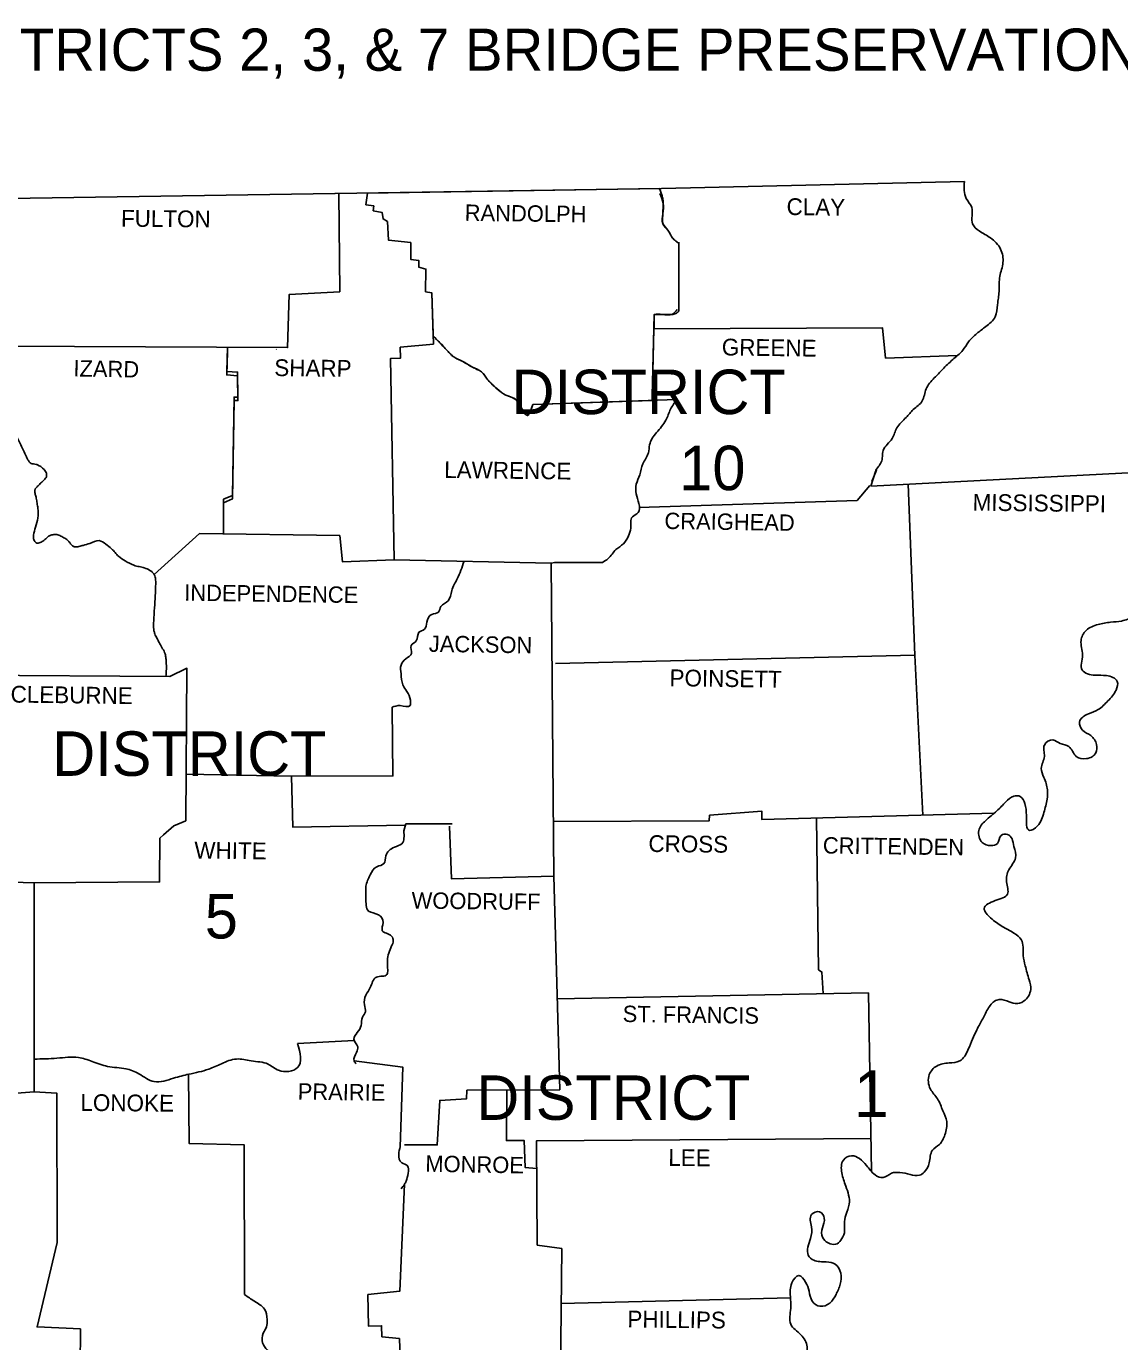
# Model space of a CAD drawing. Extents: x -12863 to 18921, y -8840 to 11152.
# Drawn here: x 13760 to 16502, y 7447 to 10747 of the extents above; entities that cross this region are included whole.
import ezdxf

# ---------------------------------------------------------------- set-up
doc = ezdxf.new("R2010")
doc.units = 0
for name, color, linetype in [('Level 1', 7, 'Continuous'), ('Level 2', 7, 'Continuous'), ('Level 3', 7, 'Continuous'), ('Level 42', 7, 'Continuous')]:
    doc.layers.add(name, color=color, linetype=linetype)

msp = doc.modelspace()

# ---------------------------------------------------------------- linework, layer by layer
at = {"layer": 'Level 1'}
for p, q in [((14615.8, 10328.9), (15347.9, 10340.3)), ((15396.7, 10202.4), (15396.7, 10032.6)), ((15878.1, 9593.9), (15889.9, 9630.1)), ((15881, 9605.6), (15892.8, 9634)), ((14711.9, 8746.6), (14828.3, 8746.6))]:
    msp.add_line(p, q, dxfattribs=at)
for points in [[(10745.4, 10313), (12327.5, 10312), (13715.8, 10314.9), (15353.7, 10340.4), (16112.9, 10358)], [(14544.5, 10327.8), (14546.5, 10081.1), (14419.3, 10074.3), (14415.4, 9941.2), (13702.7, 9945.1)], [(14780.7, 9970.4), (14777.4, 10078.2), (14761.8, 10081.1), (14762.7, 10137.9), (14745.1, 10142.7), (14745.1, 10159.4), (14724.6, 10162.3), (14724.6, 10204.4), (14668.8, 10210.3), (14665.9, 10257.2), (14655.1, 10264.1), (14653.1, 10279.7), (14630.6, 10284.6), (14631.6, 10296.4), (14612.1, 10299.3), (14615.8, 10328.9)], [(13715.8, 10309.1), (13717.8, 10076.2), (13701.2, 10075.2), (13704.1, 9831.6), (13635.6, 9821.8), (13641.5, 9756.3), (13665, 9725.9), (13663, 9648.7), (13529.9, 9643.8), (13525, 9524.4), (13403.7, 9520.5), (13397.9, 9375.7), (13404.7, 9363.9), (13407.6, 9133), (13617, 9119.3), (13614.1, 8603.7), (13780.4, 8598.8), (13780.4, 8074.4), (13649.3, 8064.6), (13639.5, 7949.2), (13419.4, 7948.2)], [(14615, 10322.8), (14612.1, 10299.3), (14631.6, 10296.4), (14630.6, 10284.6), (14653.1, 10279.7), (14655.1, 10264.1), (14665.9, 10257.2), (14668.8, 10210.3), (14724.6, 10204.4), (14724.6, 10162.3), (14745.1, 10159.4), (14745.1, 10142.7), (14762.7, 10137.9), (14761.8, 10081.1), (14777.4, 10078.2), (14781.3, 9950), (14698.2, 9942.2), (14699.1, 9914.8), (14673.7, 9913.8), (14682.5, 9408.9), (15076.8, 9400.1), (15083.6, 8615.5), (14826.3, 8608.6), (14821.4, 8740.7)], [(15396.7, 10205.4), (15396.7, 10040)], [(15335.1, 10024.4), (15329.9, 9808.8), (15030.8, 9798.3)], [(15330.2, 9819.9), (15335.1, 10024.4), (15335.1, 9988.2), (15907.5, 9991.1), (15915.3, 9914.8), (16094.8, 9921.3)], [(14264.8, 9942), (14262.8, 9881.5), (14290.2, 9879.6), (14291.1, 9816.9), (14281.4, 9816.9), (14277.4, 9570.4), (14254.9, 9560.6), (14254.9, 9478.4)], [(14387, 9936.3), (14388, 9937.3)], [(14264.7, 9929.5), (14262.8, 9872.7), (14290.2, 9870.7), (14291.1, 9808.1), (14281.4, 9808.1), (14277.4, 9561.6), (14254.9, 9551.8), (14254.9, 9473.7)], [(15030.8, 9798.3), (15391.5, 9811)], [(15878.1, 9593.9), (16620.7, 9632)], [(15296.1, 9539.9), (15843.9, 9557.7), (15876.2, 9594.8)], [(15971.8, 9598.7), (15988.7, 9169.2), (16008.6, 8768.4)], [(14080.7, 9371.9), (14194.3, 9474.5), (14546.5, 9469.6), (14553.3, 9404), (14682.5, 9409)], [(15205, 9402.1), (15085.6, 9402.1), (15076.8, 9400.1)], [(15988.7, 9169.2), (15087.6, 9148.7)], [(13617, 9119.3), (14119.9, 9116.4), (14163, 9136.9), (14160, 8754.4), (14130.7, 8741.7), (14104.3, 8719.2), (14095.5, 8710.4), (14094.5, 8600.8), (13780.4, 8598.8)], [(14677.6, 9039.1), (14679.6, 8866.9), (14425.2, 8865.9), (14160.9, 8870.9)], [(14425.2, 8865.9), (14429.1, 8737.8), (14710.8, 8742.8)], [(15082.5, 8752.4), (15473.1, 8754.4), (15474, 8768.1), (15605.1, 8777.9), (15605.1, 8757.3), (16188, 8773.3)], [(14711.9, 8746.6), (14707, 8728.9)], [(15742.1, 8761.1), (15747, 8380.6), (15755.8, 8374.8), (15758.9, 8320.6)], [(15083.6, 8615.5), (15098.3, 8079.3), (14865.5, 8078.3), (14864.5, 8056.8), (14797, 8052.9), (14791.1, 7941.3), (14708.9, 7941.3)], [(15092.1, 8307.2), (15872.2, 8322.9)], [(15872.2, 8322.9), (15880.4, 7874.7)], [(14440.8, 8195.7), (14582.7, 8202.6)], [(14582.7, 8151.7), (14705, 8136), (14698.2, 7936.4)], [(14166.9, 8119.4), (14168.8, 7944.3), (14306.8, 7941.3), (14307.8, 7565.6)], [(13780.4, 8074.4), (13837.2, 8070.5), (13838.1, 7696.7), (13787.3, 7484.4), (13895.9, 7479.5), (13894.8, 7292.5)], [(14965.3, 8078.7), (14964.3, 7952.1), (15009.3, 7952.1), (15011.2, 7884.6), (15040.1, 7881.6)], [(15095.4, 7084.2), (15171.7, 7089.1), (15170.7, 7287.8), (15099.3, 7292.6), (15103.2, 7681.1), (15041.6, 7689.9), (15039.6, 7951.1), (15878.9, 7957)], [(14708.9, 7842.5), (14697.2, 7574.4), (14616.9, 7565.6), (14618.9, 7486.4), (14651.2, 7487.3), (14652.2, 7460), (14696.2, 7455.1), (14697.6, 7407.8)], [(15101.8, 7543), (15676.7, 7557.3)]]:
    msp.add_lwpolyline(points, dxfattribs=at)
for points in [[(15347.9, 10340.3), (15349.9, 10335.8), (15351.7, 10331.2), (15354.8, 10322), (15356.8, 10312.6), (15357.2, 10310.3), (15357.4, 10307.9), (15357.6, 10303.2), (15357.5, 10296.6), (15357.2, 10290), (15356.9, 10283.4), (15356.6, 10276.8), (15356.5, 10273.7), (15356, 10264.6), (15355.9, 10258.4), (15356.2, 10255.4), (15356.4, 10253.9), (15356.5, 10253.1), (15356.6, 10252.3), (15357.4, 10249.9), (15357.9, 10248.7), (15358.6, 10247.6), (15360.3, 10245.5), (15362, 10243.6), (15365.9, 10239.7), (15367.8, 10237.8), (15369.3, 10235.7), (15372.5, 10230.6), (15375.5, 10225.4), (15378.6, 10220.2), (15380.3, 10217.6), (15382.1, 10215.1), (15384.2, 10212.7), (15386.6, 10210.4), (15389.1, 10208.4), (15396.7, 10202.4)], [(16112.9, 10358), (16117.8, 10314.9), (16131.5, 10292.4), (16133.5, 10251.3), (16150.1, 10233.7), (16178.5, 10216.1), (16203.9, 10187.8), (16209.8, 10154.5), (16202, 10120.2), (16200, 10082.1), (16196.1, 10048.8), (16190.2, 10018.5), (16166.7, 9994), (16144.2, 9976.4), (16123.7, 9955.9), (16109, 9934.3), (16083.6, 9910.9), (16058.1, 9886.4), (16037.6, 9864.9), (16017, 9837.5), (16007.3, 9807.2), (15984.8, 9785.6), (15967.1, 9766.1), (15943.7, 9739.6), (15931.9, 9713.2), (15909.4, 9682.9), (15904.5, 9653.5), (15889.9, 9630.1), (15888.9, 9626.1)], [(15348.8, 10327.7), (15357.6, 10303.2), (15356.6, 10276.8), (15356.6, 10252.3), (15369.3, 10235.7), (15382.1, 10215.1), (15391.8, 10206.3)], [(15392.8, 10037.1), (15380.1, 10024.4), (15355.6, 10024.4), (15335.1, 10024.4)], [(15396.7, 10032.6), (15394.9, 10030.9), (15393, 10029.3), (15389, 10026.7), (15384.6, 10025), (15382.4, 10024.5), (15381.3, 10024.4), (15380.1, 10024.4), (15355.6, 10024.4), (15335.1, 10024.4)], [(15030.8, 9798.3), (15029.3, 9794.1), (15027.6, 9789.2), (15023.8, 9779.4), (15019.6, 9772.4), (15017.4, 9771.1), (15016.3, 9771.2), (15015.2, 9771.9), (15014.7, 9772.4), (15014.3, 9772.8), (15013.3, 9773.8), (15011.5, 9776), (15007.8, 9781.2), (15004.1, 9786.9), (15002.3, 9789.8), (15000.5, 9792.5), (14997.8, 9796.7), (14995.2, 9800.9), (14992.6, 9805.1), (14989.7, 9809.1), (14986.6, 9812.2), (14982.8, 9814.5), (14974.3, 9817.8), (14965.4, 9820.6), (14957.4, 9824.8), (14952.2, 9828.7), (14947, 9832.8), (14941.8, 9837), (14936.9, 9841.4), (14926.4, 9851.5), (14916.3, 9861.9), (14914.4, 9864.2), (14912.7, 9866.6), (14909.4, 9871.7), (14906, 9876.5), (14901.7, 9880.5), (14900.3, 9881.4), (14899, 9882.2), (14890.5, 9886.6), (14884.8, 9889.3), (14879.2, 9892.3), (14866.4, 9899.6), (14853.7, 9906.9), (14848.3, 9909.6), (14842.7, 9911.9), (14837.2, 9914.4), (14832.2, 9917.7), (14830.9, 9918.8), (14829.7, 9919.9), (14827.3, 9922.1), (14822.7, 9926.8), (14813.6, 9936.3), (14797.1, 9953.2), (14780.7, 9970.4)], [(14792.1, 9958.8), (14813.6, 9936.3), (14832.2, 9917.7), (14853.7, 9906.9), (14879.2, 9892.3), (14901.7, 9880.5), (14916.3, 9861.9), (14936.9, 9841.4), (14957.4, 9824.8), (14989.7, 9809.1), (15000.5, 9792.5), (15015.2, 9771.9), (15030.8, 9798.3)], [(15391.5, 9811), (15376.2, 9786.6), (15364.4, 9759.2), (15341, 9727.9), (15323.4, 9697.6), (15320.4, 9677), (15306.7, 9649.6), (15298.9, 9622.2), (15290.1, 9598.8), (15290.1, 9574.3), (15296.9, 9549.8), (15295, 9527.3), (15280.3, 9516.6), (15276.4, 9488.2), (15270.5, 9468.6), (15257.8, 9449.1), (15239.2, 9434.4), (15219.6, 9411.9), (15205, 9402.1)], [(13665, 9725.9), (13674.5, 9722.3), (13684.4, 9720.3), (13694.3, 9719.5), (13704.1, 9719.1), (13710.2, 9721.1), (13716.3, 9725.5), (13722.1, 9728.9), (13724.9, 9729.2), (13727.6, 9727.9), (13733.1, 9722.3), (13737.4, 9716), (13741, 9709.3), (13744.2, 9702.5), (13753, 9682.9), (13759.8, 9668.5), (13763.5, 9661.4), (13765.5, 9657.9), (13767.7, 9654.5), (13772.3, 9650.8), (13778.5, 9649.2), (13785.1, 9648), (13788.3, 9647.1), (13791.2, 9645.7), (13808.8, 9630.1), (13811.3, 9621.6), (13810.7, 9617.2), (13808.8, 9613.4), (13805.1, 9609.4), (13801.1, 9605.6), (13797, 9601.8), (13793.1, 9597.8), (13791.4, 9595.9), (13785.8, 9590.4), (13782.8, 9586.5), (13781.8, 9584.4), (13781.4, 9582.1), (13781.7, 9577.5), (13782.8, 9572.9), (13784.2, 9568.2), (13785.3, 9563.5), (13787.4, 9550.8), (13789.2, 9538.1), (13789.2, 9513.6), (13783.3, 9491.1), (13778.5, 9470.6), (13778, 9466.1), (13778.6, 9461.7), (13780.4, 9457.3), (13781.7, 9455.1), (13783.3, 9453), (13785.4, 9451.3), (13787.6, 9450.5), (13792.5, 9451.2), (13801.9, 9455.9), (13806.8, 9459.4), (13811.5, 9463.6), (13816.2, 9467.7), (13821.5, 9470.6), (13826.5, 9471.8), (13831.8, 9472.3), (13842, 9470.6), (13852.1, 9465.7), (13861.6, 9459.8), (13866.8, 9454.9), (13871.5, 9449), (13876.3, 9443.8), (13879.1, 9442.1), (13880.6, 9441.5), (13882.2, 9441.2), (13892.4, 9442.2), (13902.7, 9445.1), (13919.3, 9450), (13942.8, 9456.9), (13959.5, 9448.1), (13974.1, 9436.3), (13978.6, 9431.8), (13982.9, 9427), (13987.1, 9422.2), (13991.7, 9417.7), (14008.4, 9406), (14029.9, 9395.2), (14036.3, 9393.1), (14043, 9391.7), (14049.7, 9390.3), (14056.3, 9388.4), (14070.2, 9382.4), (14076.1, 9377.9), (14078.6, 9375.1), (14079.8, 9373.5), (14080.8, 9371.8), (14082.4, 9368.2), (14084.7, 9357.6), (14084.9, 9350.5), (14084.7, 9343.4), (14083.7, 9318.9), (14081.8, 9288.6), (14079.8, 9255.3), (14079.4, 9247.2), (14079.4, 9239.1), (14080.4, 9231), (14081.4, 9227), (14082.7, 9223), (14087.9, 9212), (14093.5, 9201.5), (14100.4, 9189), (14107.2, 9176.1), (14110.3, 9164.5), (14110.8, 9158.6), (14111.1, 9152.6), (14111.6, 9134.5), (14110.3, 9116.5)], [(16610, 9631), (16620.7, 9632), (16654, 9596.8), (16668.7, 9567.4), (16690.2, 9550.8), (16714.7, 9542), (16733.2, 9519.5), (16746, 9495), (16739.1, 9473.5), (16711.7, 9471.6), (16681.4, 9466.7), (16652, 9467.6), (16628.6, 9448.1), (16650.1, 9421.7), (16678.4, 9397.2), (16686.3, 9370.8), (16670.6, 9345.3), (16639.3, 9331.6), (16609, 9319.9), (16581.6, 9296.4), (16568.9, 9273.9), (16538.5, 9264.1), (16507.2, 9255.3), (16479.8, 9252.4), (16448.5, 9246.5), (16418.2, 9231.8), (16405.5, 9206.4), (16409.4, 9170.2), (16408.4, 9132.1), (16440.7, 9119.3), (16469.1, 9118.4), (16496.5, 9103.7), (16493.5, 9082.2), (16473, 9054.8), (16448.5, 9033.2), (16424.1, 9022.5), (16401.6, 9001.9), (16409.4, 8981.4), (16429.9, 8967.7), (16444.6, 8945.2), (16442.7, 8924.6), (16419.2, 8910), (16393.7, 8915.8), (16375.1, 8940.3), (16353.6, 8948.1), (16335, 8956.9), (16313.5, 8944.2), (16313.5, 8915.8), (16305.7, 8885.5), (16312.5, 8863), (16321.3, 8831.7), (16320.4, 8808.2), (16312.5, 8774.9), (16295.9, 8740.7), (16276.3, 8729.9), (16268.5, 8767.1), (16264.6, 8797.4), (16252.8, 8815), (16237.2, 8816), (16216.6, 8801.3), (16194.1, 8778.8), (16165.8, 8754.4), (16149.1, 8729.9), (16157.9, 8699.6), (16179.5, 8691.8), (16196.1, 8697.6), (16204.9, 8717.2), (16221.5, 8720.1), (16237.2, 8689.8)], [(14858.1, 9405.1), (14841, 9361), (14827.3, 9331.6), (14818.5, 9306.2), (14799.9, 9291.5), (14794, 9277.8), (14777.4, 9272), (14764.7, 9252.4), (14758.8, 9234.8), (14745.1, 9227), (14738.3, 9205.4), (14725.5, 9193.7), (14726.5, 9174.1), (14711.9, 9160.4), (14700.1, 9144.8), (14700.1, 9123.2), (14705, 9094.9), (14714.8, 9078.2), (14723.6, 9056.7), (14722.6, 9043), (14698.2, 9043), (14677.6, 9039.1)], [(14707, 8728.9), (14702.1, 8696.7), (14683.5, 8687.9), (14662, 8666.3), (14657.1, 8646.8), (14639.4, 8638.9), (14622.8, 8618.4), (14612.1, 8590), (14612.1, 8560.7), (14618.9, 8527.4), (14643.4, 8518.6), (14655.1, 8499), (14653.1, 8478.5), (14676.6, 8464.8), (14680.5, 8453), (14676.6, 8440.3), (14665.9, 8404.1), (14666.8, 8379.7), (14664.9, 8368.9), (14638.5, 8362), (14622.8, 8335.6), (14612.1, 8317), (14608.1, 8292.6), (14611.1, 8275), (14603.2, 8261.3), (14600.3, 8240.7), (14590.5, 8223.1), (14581.7, 8206.5), (14591.5, 8186.9), (14588.6, 8173.2), (14582.7, 8151.7), (14587.6, 8144.8)], [(16237.2, 8689.8), (16241.1, 8661.4), (16224.5, 8631.1), (16218.6, 8600.8), (16221.5, 8570.4), (16190.2, 8553.8), (16162.8, 8534.2), (16178.5, 8510.8), (16207.8, 8489.2), (16237.2, 8472.6), (16255.8, 8456), (16260.7, 8415.9), (16265.6, 8390.4), (16275.3, 8355.2), (16279.3, 8330.7), (16261.6, 8301.4), (16241.1, 8295.5), (16219.6, 8302.4), (16194.1, 8304.3), (16173.6, 8284.8), (16158.9, 8257.4), (16144.2, 8230), (16133.5, 8206.5), (16122.7, 8181), (16101.2, 8151.7), (16074.8, 8146.8), (16043.5, 8139), (16024.9, 8117.4), (16027.8, 8081.2), (16045.4, 8056.8), (16059.1, 8026.5), (16068.9, 8000), (16064, 7966.8), (16050.3, 7942.3), (16032.7, 7927.6), (16024.9, 7896.3), (16012.2, 7872.8), (16000.4, 7865), (15976.9, 7867), (15951.5, 7871.9), (15930, 7869.9), (15909.4, 7859.1), (15888.9, 7866), (15867.4, 7889.5), (15849.7, 7907.1), (15830.2, 7913.9), (15809.6, 7903.2), (15805.7, 7870.9), (15815.5, 7837.6), (15824.3, 7792.6), (15815.5, 7765.2), (15812.6, 7720.2)], [(13780, 8156.5), (13837.2, 8158.5), (13891, 8160.5), (13925.2, 8150.7), (13964.3, 8138), (14010.3, 8132.1), (14042.6, 8119.4), (14080.8, 8099.8), (14129.7, 8108.6), (14167.9, 8118.4), (14217.8, 8131.1), (14250, 8144.8), (14287.2, 8156.6), (14324.4, 8151.7), (14366.5, 8143.9), (14392.9, 8128.2), (14440.8, 8135.1), (14440.8, 8195.7)], [(14698.2, 7936.4), (14694.2, 7916.9), (14702.1, 7896.3), (14715.8, 7889.5), (14717.7, 7869.9), (14712.8, 7850.3), (14708.9, 7842.5), (14700.1, 7830.8)], [(15812.6, 7720.2), (15790.1, 7691.8), (15756.8, 7709.4), (15756.8, 7732.9), (15761.7, 7757.4), (15749.9, 7773), (15729.4, 7766.2), (15729.4, 7735.9), (15727.4, 7706.5), (15721.6, 7664.4), (15735.3, 7651.7), (15766.6, 7647.8), (15789.1, 7641.9), (15802.8, 7619.4), (15801.8, 7592), (15791, 7565.6), (15775.4, 7544.1), (15750.9, 7536.3), (15731.4, 7549), (15723.5, 7574.4), (15714.7, 7596.9), (15698.1, 7613.6), (15680.5, 7595), (15676.6, 7560.7), (15677.5, 7531.4), (15677.5, 7491.3), (15703, 7464.8), (15718.6, 7434.5), (15713.7, 7407.1), (15695.2, 7374.8), (15687.3, 7346.5), (15679.5, 7308.3), (15680.5, 7266.2), (15673.6, 7225.1), (15659.9, 7197.7), (15634.5, 7175.2), (15617.9, 7160.6), (15604.2, 7145.9), (15597.3, 7116.5), (15592.4, 7096), (15573.8, 7071.5), (15559.2, 7069.6), (15547.4, 7079.4), (15543.5, 7096), (15543.5, 7112.6), (15535.7, 7129.3), (15511.2, 7136.1), (15491.6, 7135.1), (15482.8, 7121.4), (15495.6, 7083.3), (15500.4, 7058.8), (15493.6, 7025.5), (15497.5, 7021.6), (15462.3, 7003), (15433.9, 7000.1), (15410.4, 6993.3), (15387.9, 6978.6), (15377.2, 6957.1), (15361.5, 6939.4), (15347.8, 6922.8), (15329.2, 6915), (15308.7, 6918.9), (15281.3, 6921.8), (15265.6, 6902.3), (15270.5, 6873.9), (15289.1, 6857.3), (15316.5, 6849.4), (15344.9, 6851.4), (15372.3, 6854.3), (15397.7, 6840.6), (15392.8, 6814.2), (15368.4, 6801.5), (15332.2, 6797.6), (15302.8, 6800.5), (15267.6, 6792.7), (15250, 6770.2), (15259.8, 6735.9), (15297.9, 6722.2), (15315.5, 6689.9), (15316.5, 6659.6), (15303.8, 6619.5), (15286.2, 6600.9), (15251.9, 6593.1), (15225.5, 6588.2), (15221.6, 6543.2), (15209.9, 6520.7), (15189.3, 6513.8), (15160, 6528.5), (15142.4, 6535.4), (15120.8, 6545.1), (15093.4, 6561.8), (15072.9, 6558.8), (15078.8, 6515.8), (15080.7, 6513.8), (15104.2, 6481.5), (15127.7, 6456.1), (15138.4, 6425.8)], [(14307.8, 7565.6), (14332.2, 7549), (14357.7, 7529.4), (14364.5, 7503), (14362.6, 7484.4), (14354.7, 7468.8), (14352.8, 7444.3), (14364.5, 7426.7), (14375.3, 7412), (14364.5, 7385.6), (14345.9, 7361.1), (14336.1, 7333.7), (14329.3, 7292.6)]]:
    msp.add_spline(points, degree=3, dxfattribs=at)

# ---------------------------------------------------------------- texts
msp.add_text('1', height=117.4, dxfattribs=at).set_placement((15836, 8010.8))
at = {"layer": 'Level 2'}
for s, height, rotation, p in [('RANDOLPH', 41.09, 359.2583, (14859.6, 10259.2)), ('CLAY', 42.06, 359.2258, (15666.8, 10273.9)), ('FULTON', 42.06, 359.4996, (13997.6, 10244.5)), ('GREENE', 42.07, 359.2361, (15504.4, 9921.6)), ('IZARD', 41.08, 358.9258, (13878.2, 9868.8)), ('SHARP', 42.06, 359.3905, (14382.1, 9869.8)), ('LAWRENCE', 42.07, 359.2678, (14808.2, 9614.2)), ('MISSISSIPPI', 42.062, 359.3097, (16133.5, 9532.2)), ('CRAIGHEAD', 41.09, 359.1159, (15360.5, 9486.2)), ('INDEPENDENCE', 41.081, 359.2187, (14156.1, 9306.2)), ('JACKSON', 41.08, 359.1352, (14769.6, 9178)), ('POINSETT', 42.06, 359.1987, (15373.3, 9091.9)), ('CLEBURNE', 42.06, 359.2535, (13720.7, 9050.8)), ('CROSS', 42.06, 359.3839, (15320.4, 8676.1)), ('CRITTENDEN', 41.09, 359.213, (15757.8, 8672.2)), ('WHITE', 42.07, 359.3139, (14181.6, 8659.5)), ('WOODRUFF', 41.08, 359.2748, (14726.5, 8534.2)), ('ST. FRANCIS', 41.081, 359.2216, (15255.8, 8249.5)), ('PRAIRIE', 41.09, 359.2116, (14440.8, 8054.8)), ('LONOKE', 42.07, 359.4974, (13895.9, 8026.5)), ('LEE', 42.07, 359.4327, (15370.3, 7888.5)), ('MONROE', 41.08, 359.0331, (14760.8, 7873.8)), ('PHILLIPS', 42.06, 359.3179, (15267.6, 7483.4))]:
    msp.add_text(s, height=height, rotation=rotation, dxfattribs=at).set_placement(p)
at = {"layer": 'Level 3'}
for s, height, p in [('DISTRICT', 111.54, (14977.3, 9774.3)), ('10', 111.54, (15398, 9583.5)), ('DISTRICT', 111.54, (13825.4, 8866.9)), ('5', 111.5, (14208, 8458.9)), ('DISTRICT', 111.54, (14888.9, 8003.9))]:
    msp.add_text(s, height=height, dxfattribs=at).set_placement(p)
at = {"layer": 'Level 42'}
msp.add_text('DISTRICTS 2, 3, & 7 BRIDGE PRESERVATION (2022) (S)', height=105.809, dxfattribs=at).set_placement((13508, 10635.6))

doc.saveas('drawing.dxf')
